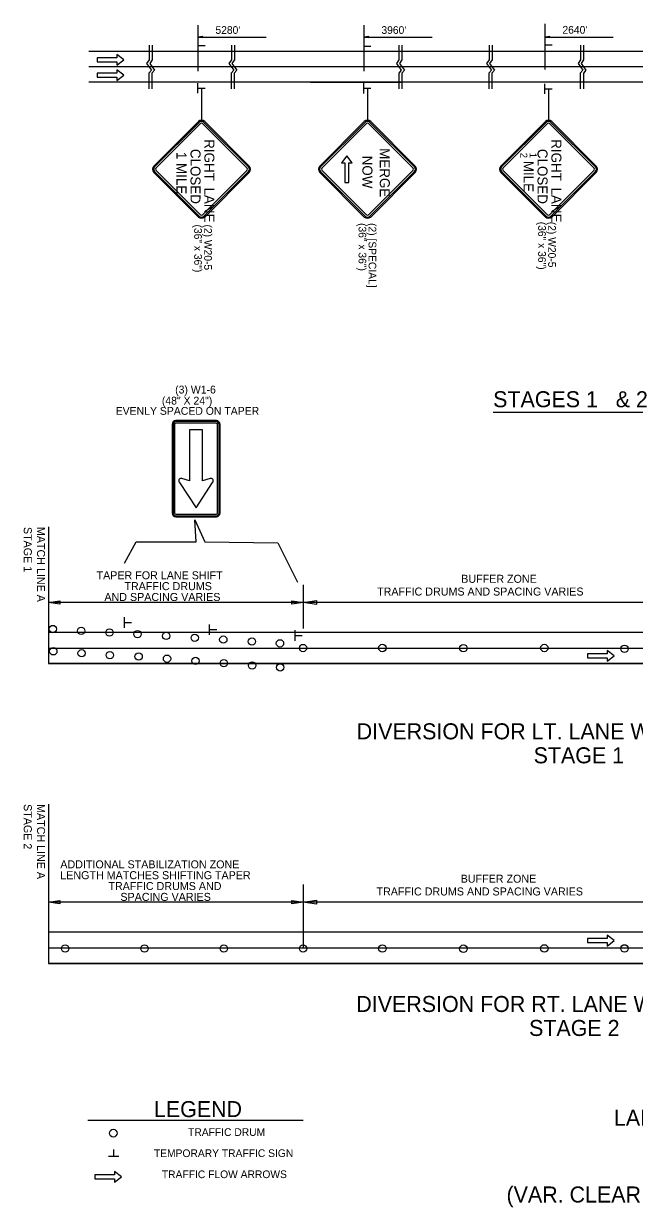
# Model space of a CAD drawing. Extents: x 1930579 to 1938745, y 596452 to 597559.
# Drawn here: x 1936678 to 1937136, y 596540 to 597428 of the extents above; entities that cross this region are included whole.
import ezdxf

# ---------------------------------------------------------------- set-up
doc = ezdxf.new("R2010")
doc.units = 0
for name, color, linetype in [('Default', 7, 'Continuous'), ('P_TC_Signs_Permanent', 7, 'Continuous'), ('P_TC_Signs_Temporary', 7, 'Continuous'), ('R_Annotation', 7, 'Continuous'), ('R_MOT', 7, 'Continuous'), ('R_Striping', 7, 'Continuous')]:
    doc.layers.add(name, color=color, linetype=linetype)

msp = doc.modelspace()

# ---------------------------------------------------------------- linework, layer by layer
at = {"layer": 'Default'}
for p, q in [((1936808.49, 597426.38), (1936808.49, 597391.9)), ((1936932.85, 597426.38), (1936932.85, 597391.9)), ((1937068.5, 597427.55), (1937068.5, 597393.08)), ((1936812.16, 597417.99), (1936808.49, 597417.44)), ((1936808.49, 597417.44), (1936859.59, 597417.44)), ((1936812.16, 597416.89), (1936808.49, 597417.44)), ((1936808.49, 597414.91), (1936808.49, 597407.25)), ((1936812.16, 597417.9), (1936809.1, 597417.44)), ((1936812.16, 597416.98), (1936809.1, 597417.44)), ((1936812.16, 597417.81), (1936809.73, 597417.44)), ((1936812.16, 597417.08), (1936809.73, 597417.44)), ((1936812.16, 597417.72), (1936810.34, 597417.44)), ((1936812.16, 597417.17), (1936810.34, 597417.44)), ((1936812.16, 597417.62), (1936810.96, 597417.44)), ((1936812.16, 597417.27), (1936810.96, 597417.44)), ((1936812.16, 597417.53), (1936811.58, 597417.44)), ((1936812.16, 597417.36), (1936811.58, 597417.44)), ((1936812.16, 597416.89), (1936812.16, 597417.99)), ((1936936.53, 597417.99), (1936932.85, 597417.44)), ((1936932.85, 597417.44), (1936983.96, 597417.44)), ((1936936.53, 597416.89), (1936932.85, 597417.44)), ((1936932.85, 597414.4), (1936932.85, 597406.74)), ((1936936.53, 597417.9), (1936933.47, 597417.44)), ((1936936.53, 597416.98), (1936933.47, 597417.44)), ((1936936.53, 597417.81), (1936934.1, 597417.44)), ((1936936.53, 597417.08), (1936934.1, 597417.44)), ((1936936.53, 597417.72), (1936934.71, 597417.44)), ((1936936.53, 597417.17), (1936934.71, 597417.44)), ((1936936.53, 597417.62), (1936935.33, 597417.44)), ((1936936.53, 597417.27), (1936935.33, 597417.44)), ((1936936.53, 597417.53), (1936935.95, 597417.44)), ((1936936.53, 597417.36), (1936935.95, 597417.44)), ((1936936.53, 597416.89), (1936936.53, 597417.99)), ((1937072.18, 597417.99), (1937068.5, 597417.44)), ((1937068.5, 597417.44), (1937119.61, 597417.44)), ((1937072.18, 597416.89), (1937068.5, 597417.44)), ((1937068.5, 597415.4), (1937068.5, 597407.74)), ((1937068.62, 597411.59), (1937073.85, 597411.59)), ((1937072.18, 597417.9), (1937069.12, 597417.44)), ((1937072.18, 597416.98), (1937069.12, 597417.44)), ((1937072.18, 597417.81), (1937069.75, 597417.44)), ((1937072.18, 597417.08), (1937069.75, 597417.44)), ((1937072.18, 597417.72), (1937070.36, 597417.44)), ((1937072.18, 597417.17), (1937070.36, 597417.44)), ((1937072.18, 597417.62), (1937070.98, 597417.44)), ((1937072.18, 597417.27), (1937070.98, 597417.44)), ((1937072.18, 597417.53), (1937071.6, 597417.44)), ((1937072.18, 597417.36), (1937071.6, 597417.44)), ((1937072.18, 597416.89), (1937072.18, 597417.99)), ((1937394.52, 597406.66), (1936726.79, 597406.66)), ((1936808.6, 597411.1), (1936813.83, 597411.1)), ((1936932.97, 597410.59), (1936938.2, 597410.59)), ((1938013.48, 597395.14), (1936726.79, 597395.14)), ((1937394.52, 597383.62), (1936726.79, 597383.62)), ((1936808.49, 597375.36), (1936808.49, 597383.02)), ((1936808.6, 597379.17), (1936813.83, 597379.17)), ((1936892.9, 597383.62), (1936960.47, 597383.62)), ((1936932.85, 597375.31), (1936932.85, 597382.97)), ((1936932.97, 597379.12), (1936938.2, 597379.12)), ((1937068.5, 597374.88), (1937068.5, 597382.54)), ((1937068.62, 597378.69), (1937073.85, 597378.69)), ((1937029.73, 597136.48), (1937158.05, 597136.48)), ((1936696.54, 597050.33), (1936696.54, 596947.87)), ((1936887.3, 597006.91), (1936887.3, 596974.28)), ((1936696.54, 596993.7), (1936705.03, 596994.97)), ((1936705.03, 596994.97), (1936705.03, 596992.42)), ((1936878.81, 596992.42), (1936878.81, 596994.97)), ((1936878.81, 596994.97), (1936887.3, 596993.7)), ((1936887.38, 596993.7), (1936897.44, 596995.21)), ((1936897.44, 596995.21), (1936897.44, 596992.19)), ((1936887.3, 596993.7), (1936696.54, 596993.7)), ((1936705.03, 596992.42), (1936696.54, 596993.7)), ((1936887.3, 596993.7), (1936878.81, 596992.42)), ((1937188.67, 596993.7), (1936887.3, 596993.7)), ((1936897.44, 596992.19), (1936887.38, 596993.7)), ((1936753.38, 596974.79), (1936753.38, 596982.58)), ((1936753.49, 596978.66), (1936758.81, 596978.66)), ((1936817.26, 596969.5), (1936817.26, 596977.29)), ((1937643.39, 596971.31), (1936696.54, 596971.31)), ((1936817.37, 596973.37), (1936822.69, 596973.37)), ((1936881.28, 596965.09), (1936881.28, 596972.88)), ((1936881.4, 596968.97), (1936886.72, 596968.97)), ((1936696.54, 596959.59), (1937643.39, 596959.59)), ((1936696.54, 596947.87), (1936970.48, 596947.87)), ((1937643.39, 596947.87), (1936696.54, 596947.87)), ((1936954.98, 596947.87), (1937223.6, 596947.87)), ((1936696.54, 596842.59), (1936696.54, 596723.17)), ((1936887.3, 596782.21), (1936887.3, 596734.89)), ((1936696.54, 596769), (1936705.03, 596770.27)), ((1936887.3, 596769), (1936696.54, 596769)), ((1936705.03, 596767.72), (1936696.54, 596769)), ((1936705.03, 596770.27), (1936705.03, 596767.72)), ((1936878.81, 596767.72), (1936878.81, 596770.27)), ((1936878.81, 596770.27), (1936887.3, 596769)), ((1936887.3, 596769), (1936878.81, 596767.72)), ((1937188.67, 596769), (1936887.3, 596769)), ((1936887.38, 596769), (1936897.44, 596770.51)), ((1936897.44, 596767.49), (1936887.38, 596769)), ((1936897.44, 596770.51), (1936897.44, 596767.49)), ((1937643.39, 596746.61), (1936696.54, 596746.61)), ((1936696.54, 596734.89), (1937643.39, 596734.89)), ((1936696.54, 596723.17), (1936970.48, 596723.17)), ((1937643.39, 596723.17), (1936696.54, 596723.17)), ((1936954.98, 596723.17), (1937223.6, 596723.17))]:
    msp.add_line(p, q, dxfattribs=at)
for points in [[(1936771.93, 597411.46), (1936771.93, 597400.51), (1936770.06, 597397.73), (1936773.71, 597392.74), (1936771.79, 597390.44), (1936771.79, 597378.82)], [(1936774.24, 597411.46), (1936774.24, 597400.41), (1936772.36, 597397.63), (1936776.01, 597392.65), (1936774.09, 597390.34), (1936774.09, 597378.82)], [(1936833.61, 597411.46), (1936833.61, 597400.51), (1936831.73, 597397.73), (1936835.38, 597392.74), (1936833.46, 597390.44), (1936833.46, 597378.82)], [(1936835.91, 597411.46), (1936835.91, 597400.41), (1936834.04, 597397.63), (1936837.68, 597392.65), (1936835.76, 597390.34), (1936835.76, 597378.82)], [(1936959.1, 597411.46), (1936959.1, 597400.51), (1936957.23, 597397.73), (1936960.88, 597392.74), (1936958.96, 597390.44), (1936958.95, 597378.82)], [(1936961.4, 597411.46), (1936961.4, 597400.41), (1936959.53, 597397.63), (1936963.18, 597392.65), (1936961.26, 597390.34), (1936961.26, 597378.82)], [(1937026.67, 597411.46), (1937026.67, 597400.51), (1937024.8, 597397.73), (1937028.44, 597392.74), (1937026.52, 597390.44), (1937026.52, 597378.82)], [(1937028.97, 597411.46), (1937028.97, 597400.41), (1937027.1, 597397.63), (1937030.74, 597392.65), (1937028.83, 597390.34), (1937028.82, 597378.82)], [(1937095.18, 597411.46), (1937095.18, 597400.51), (1937093.31, 597397.73), (1937096.95, 597392.74), (1937095.03, 597390.44), (1937095.03, 597378.82)], [(1937097.48, 597411.46), (1937097.48, 597400.41), (1937095.61, 597397.63), (1937099.25, 597392.65), (1937097.33, 597390.34), (1937097.33, 597378.82)]]:
    msp.add_lwpolyline(points, dxfattribs=at)
for centre, radius in [((1936699.79, 596973.82), 2.75), ((1936721.02, 596972.51), 2.75), ((1936742.25, 596971.19), 2.75), ((1936763.24, 596970.03), 2.75), ((1936784.68, 596968.65), 2.75), ((1936806.12, 596967.26), 2.75), ((1936827.55, 596965.88), 2.75), ((1936700.15, 596957.12), 2.75), ((1936848.99, 596964.5), 2.75), ((1936869.99, 596963.06), 2.75), ((1936887.3, 596959.59), 2.75), ((1936946.73, 596959.59), 2.8), ((1937007.41, 596959.44), 2.8), ((1937068.09, 596959.59), 2.8), ((1937128.13, 596959.01), 2.8), ((1936721.36, 596955.65), 2.75), ((1936742.58, 596954.17), 2.75), ((1936764.09, 596953.25), 2.75), ((1936785.37, 596951.58), 2.75), ((1936806.65, 596949.9), 2.75), ((1936827.93, 596948.22), 2.75), ((1936849.21, 596946.54), 2.75), ((1936870.19, 596945.08), 2.75), ((1936946.73, 596734.35), 2.8), ((1937068.09, 596734.41), 2.8), ((1937128.13, 596734.42), 2.8), ((1936709.01, 596734.35), 2.75), ((1936768.44, 596734.35), 2.75), ((1936827.87, 596734.35), 2.75), ((1936887.3, 596734.35), 2.75), ((1937007.41, 596734.21), 2.8), ((1936745.07, 596595.94), 2.88)]:
    msp.add_circle(centre, radius, dxfattribs=at)
at = {"layer": 'P_TC_Signs_Permanent'}
for p, q in [((1936822.32, 597129.99), (1936791.95, 597129.99)), ((1936822.32, 597129.24), (1936791.95, 597129.24)), ((1936822.32, 597128.12), (1936791.95, 597128.12)), ((1936789.13, 597127.18), (1936789.13, 597060.81)), ((1936789.88, 597127.18), (1936789.88, 597060.81)), ((1936791.01, 597127.18), (1936791.01, 597060.81)), ((1936823.26, 597060.81), (1936823.26, 597127.18)), ((1936824.38, 597060.81), (1936824.38, 597127.18)), ((1936825.13, 597060.81), (1936825.13, 597127.18)), ((1936791.95, 597059.87), (1936822.32, 597059.87)), ((1936791.95, 597058.74), (1936822.32, 597058.74)), ((1936791.95, 597057.99), (1936822.32, 597057.99))]:
    msp.add_line(p, q, dxfattribs=at)
for points in [[(1936817.77, 597086.7), (1936812.01, 597084.98), (1936812.01, 597123.24), (1936802.26, 597123.24), (1936802.26, 597084.98), (1936796.51, 597086.73)], [(1936794.69, 597083.74), (1936807.13, 597064.74), (1936819.54, 597083.75)]]:
    msp.add_lwpolyline(points, dxfattribs=at)
for centre, radius, start, end in [((1936791.95, 597127.18), 2.81, 90, 180), ((1936791.95, 597127.18), 2.06, 90, 180), ((1936791.95, 597127.18), 0.938, 90, 180), ((1936822.32, 597127.18), 2.81, 360, 90), ((1936822.32, 597127.18), 2.06, 360, 90), ((1936822.32, 597127.18), 0.937, 360, 90), ((1936796.02, 597085), 1.8, 74.03093, 213.47548), ((1936731.96, 597042.64), 75, 33.2286, 33.47548), ((1936818.25, 597085), 1.76, 326.59943, 105.96908), ((1936882.34, 597042.74), 75, 146.59943, 146.85697), ((1936791.95, 597060.81), 2.81, 180, 270), ((1936791.95, 597060.81), 2.06, 180, 270), ((1936791.95, 597060.81), 0.938, 180, 270), ((1936822.32, 597060.81), 2.81, 270, 360), ((1936822.32, 597060.81), 2.06, 270, 360), ((1936822.32, 597060.81), 0.938, 270, 360)]:
    msp.add_arc(centre, radius, start, end, dxfattribs=at)
at = {"layer": 'P_TC_Signs_Temporary'}
for p, q in [((1936775.42, 597320.83), (1936808.83, 597354.24)), ((1936776.08, 597320.16), (1936809.49, 597353.57)), ((1936777.01, 597319.23), (1936810.42, 597352.65)), ((1936812.01, 597352.65), (1936845.42, 597319.23)), ((1936812.94, 597353.57), (1936846.35, 597320.16)), ((1936813.6, 597354.24), (1936847.01, 597320.83)), ((1936899.78, 597320.83), (1936933.2, 597354.24)), ((1936900.45, 597320.16), (1936933.86, 597353.57)), ((1936901.38, 597319.23), (1936934.79, 597352.65)), ((1936936.38, 597352.65), (1936969.79, 597319.23)), ((1936937.31, 597353.57), (1936970.72, 597320.16)), ((1936937.97, 597354.24), (1936971.38, 597320.83)), ((1937035.43, 597320.83), (1937068.84, 597354.24)), ((1937036.1, 597320.16), (1937069.51, 597353.57)), ((1937037.03, 597319.23), (1937070.44, 597352.65)), ((1937072.03, 597352.65), (1937105.44, 597319.23)), ((1937072.95, 597353.57), (1937106.37, 597320.16)), ((1937073.62, 597354.24), (1937107.03, 597320.83)), ((1936808.83, 597282.64), (1936775.42, 597316.05)), ((1936809.49, 597283.3), (1936776.08, 597316.72)), ((1936810.42, 597284.23), (1936777.01, 597317.64)), ((1936845.42, 597317.64), (1936812.01, 597284.23)), ((1936846.35, 597316.72), (1936812.94, 597283.3)), ((1936847.01, 597316.05), (1936813.6, 597282.64)), ((1936933.2, 597282.64), (1936899.78, 597316.05)), ((1936933.86, 597283.3), (1936900.45, 597316.72)), ((1936934.79, 597284.23), (1936901.38, 597317.64)), ((1936969.79, 597317.64), (1936936.38, 597284.23)), ((1936970.72, 597316.72), (1936937.31, 597283.3)), ((1936971.38, 597316.05), (1936937.97, 597282.64)), ((1937068.84, 597282.64), (1937035.43, 597316.05)), ((1937069.51, 597283.3), (1937036.1, 597316.72)), ((1937070.44, 597284.23), (1937037.03, 597317.64)), ((1937105.44, 597317.64), (1937072.03, 597284.23)), ((1937106.37, 597316.72), (1937072.95, 597283.3)), ((1937107.03, 597316.05), (1937073.62, 597282.64))]:
    msp.add_line(p, q, dxfattribs=at)
for centre, radius, start, end in [((1936811.21, 597351.85), 3.37, 45, 135), ((1936811.21, 597351.85), 2.44, 45, 135), ((1936811.21, 597351.85), 1.12, 45, 135), ((1936935.58, 597351.85), 3.37, 45, 135), ((1936935.58, 597351.85), 2.44, 45, 135), ((1936935.58, 597351.85), 1.12, 45, 135), ((1937071.23, 597351.85), 3.37, 45, 135), ((1937071.23, 597351.85), 2.44, 45, 135), ((1937071.23, 597351.85), 1.12, 45, 135), ((1936777.8, 597318.44), 3.37, 135, 225), ((1936777.8, 597318.44), 2.44, 135, 225), ((1936777.8, 597318.44), 1.13, 135, 225), ((1936844.62, 597318.44), 1.13, 315, 45), ((1936844.62, 597318.44), 2.44, 315, 45), ((1936844.62, 597318.44), 3.38, 315, 45), ((1936902.17, 597318.44), 3.37, 135, 225), ((1936902.17, 597318.44), 2.44, 135, 225), ((1936902.17, 597318.44), 1.13, 135, 225), ((1936968.99, 597318.44), 1.13, 315, 45), ((1936968.99, 597318.44), 2.44, 315, 45), ((1936968.99, 597318.44), 3.38, 315, 45), ((1937037.82, 597318.44), 3.37, 135, 225), ((1937037.82, 597318.44), 2.44, 135, 225), ((1937037.82, 597318.44), 1.13, 135, 225), ((1937104.64, 597318.44), 1.13, 315, 45), ((1937104.64, 597318.44), 2.44, 315, 45), ((1937104.64, 597318.44), 3.37, 315, 45), ((1936811.21, 597285.03), 3.38, 225, 315), ((1936811.21, 597285.03), 2.44, 225, 315), ((1936811.21, 597285.03), 1.12, 225, 315), ((1936935.58, 597285.03), 3.38, 225, 315), ((1936935.58, 597285.03), 2.44, 225, 315), ((1936935.58, 597285.03), 1.12, 225, 315), ((1937071.23, 597285.03), 3.37, 225, 315), ((1937071.23, 597285.03), 2.44, 225, 315), ((1937071.23, 597285.03), 1.12, 225, 315)]:
    msp.add_arc(centre, radius, start, end, dxfattribs=at)
at = {"layer": 'R_Annotation'}
for p, q in [((1936811.21, 597379.17), (1936811.21, 597355.22)), ((1936935.58, 597379.12), (1936935.58, 597355.22)), ((1937071.23, 597378.69), (1937071.23, 597355.22)), ((1936726.09, 596605.58), (1936887.49, 596605.69)), ((1936749.26, 596578.39), (1936741.58, 596578.39)), ((1936745.44, 596578.5), (1936745.44, 596583.74))]:
    msp.add_line(p, q, dxfattribs=at)
msp.add_lwpolyline([(1936753.38, 597023.29), (1936762.17, 597039.21), (1936807.32, 597039.21), (1936806.15, 597055.7), (1936813.77, 597039.21), (1936868.47, 597038.42), (1936883.18, 597008.99)], dxfattribs=at)
at = {"layer": 'R_MOT'}
for points in [[(1936924.09, 597323.31), (1936920.09, 597328.5), (1936916.09, 597323.31), (1936918.59, 597323.31), (1936918.59, 597308.59), (1936921.59, 597308.59), (1936921.59, 597323.31)], [(1936746.07, 596559.17), (1936751.26, 596563.18), (1936746.07, 596567.17), (1936746.07, 596564.67), (1936731.36, 596564.66), (1936731.36, 596561.66), (1936746.07, 596561.67)]]:
    msp.add_lwpolyline(points, close=True, dxfattribs=at)
at = {"layer": 'R_Striping'}
for points in [[(1936747.79, 597396.34), (1936752.99, 597400.34), (1936747.79, 597404.34), (1936747.79, 597401.84), (1936733.08, 597401.84), (1936733.08, 597398.84), (1936747.79, 597398.84)], [(1936747.79, 597385.03), (1936752.99, 597389.03), (1936747.79, 597393.03), (1936747.79, 597390.53), (1936733.08, 597390.53), (1936733.08, 597387.53), (1936747.79, 597387.53)], [(1937115.13, 596949.68), (1937120.32, 596953.68), (1937115.13, 596957.68), (1937115.13, 596955.18), (1937100.41, 596955.18), (1937100.41, 596952.18), (1937115.13, 596952.18)], [(1937115.13, 596736.23), (1937120.32, 596740.23), (1937115.13, 596744.23), (1937115.13, 596741.73), (1937100.41, 596741.73), (1937100.41, 596738.73), (1937115.13, 596738.73)]]:
    msp.add_lwpolyline(points, close=True, dxfattribs=at)

# ---------------------------------------------------------------- texts
at = {"layer": 'Default'}
for s, height, rotation, p in [("5280'", 5.76, 360, (1936821.65, 597419.92)), ("3960'", 5.76, 360, (1936946.02, 597419.9)), ("2640'", 5.76, 360, (1937081.67, 597420.05)), ('STAGES 1   & 2', 12, 360, (1937029.73, 597140.05)), ('STAGE 1', 6, 270, (1936678.04, 597050.33)), ('MATCH LINE A ', 6, 270, (1936687.95, 597050.33)), ('TAPER FOR LANE SHIFT', 6, 360, (1936732.57, 597011.09)), ('BUFFER ZONE', 6, 360, (1937005.82, 597008.47)), ('TRAFFIC DRUMS ', 6, 360, (1936753.44, 597002.97)), ('TRAFFIC DRUMS AND SPACING VARIES', 6, 360, (1936942.76, 596998.9)), ('AND SPACING VARIES', 6, 360, (1936738.44, 596994.84)), ('DIVERSION FOR LT. LANE WORK ZONE', 12, 360, (1936927.5, 596891.14)), ('STAGE 1', 12, 360, (1937060.06, 596873.16)), ('STAGE 2', 6, 270, (1936678.04, 596842.59)), ('MATCH LINE A ', 6, 270, (1936687.95, 596842.59)), ('ADDITIONAL STABILIZATION ZONE', 6, 360, (1936705.41, 596794.42)), ('LENGTH MATCHES SHIFTING TAPER', 6, 360, (1936705.38, 596786.3)), ('TRAFFIC DRUMS AND ', 6, 360, (1936741.46, 596778.17)), ('BUFFER ZONE', 6, 360, (1937005.42, 596783.68)), ('SPACING VARIES', 6, 360, (1936750.44, 596770.04)), ('TRAFFIC DRUMS AND SPACING VARIES', 6, 360, (1936942.35, 596774.11)), ('DIVERSION FOR RT. LANE WORK ZONE', 12, 360, (1936927.21, 596686.77)), ('STAGE 2', 12, 360, (1937056.66, 596668.8)), ('LANE CLOSURE WITH TRAFFIC DRUMS', 12, 360, (1937120.24, 596601.57)), ('(VAR. CLEAR ROADWAY WIDTHS ON THE BRIDGE DECKS)', 12, 360, (1937039.74, 596543.97))]:
    msp.add_text(s, height=height, rotation=rotation, dxfattribs=at).set_placement(p)
at = {"layer": 'P_TC_Signs_Temporary'}
for s, height, p in [('CLOSED', 7.5, (1936802.96, 597333.69)), ('RIGHT\u2002LANE', 7.5, (1936813.34, 597340.96)), ('MERGE', 7.5, (1936944.79, 597334.2)), ('CLOSED', 7.5, (1937062.98, 597333.69)), ('RIGHT\u2002LANE', 7.5, (1937073.36, 597340.96)), ('1 MILE', 7.5, (1936792.46, 597331.49)), ('NOW', 7.5, (1936931.77, 597328.6)), ('2', 5.25, (1937050.11, 597330.79)), (' MILE', 7.5, (1937052.48, 597327.53)), ('1', 5.25, (1937057.11, 597330.79))]:
    msp.add_text(s, height=height, rotation=270, dxfattribs=at).set_placement(p)
at = {"layer": 'R_Annotation'}
for s, height, rotation, p in [('(36" x 36")', 5.76, 270, (1937063.47, 597279.07)), ('(2) W20-5', 5.76, 270, (1937070.96, 597279.07)), ('(36" x 36")', 5.76, 270, (1936805.73, 597277.02)), ('(2) W20-5', 5.76, 270, (1936813.22, 597277.02)), ('(36" x 36")', 5.76, 270, (1936928.89, 597278.09)), ('(2) [SPECIAL]', 5.76, 270, (1936936.38, 597278.09)), ('(3) W1-6', 5.859, 0.00754, (1936791.46, 597150.34)), ('(48" X 24")', 5.8594, 0.00754, (1936781.48, 597142.07)), ('EVENLY SPACED ON TAPER', 5.8594, 0.00754, (1936746.9, 597134.38)), ('LEGEND', 12, 0.03878, (1936775.57, 596607.95)), ('TRAFFIC DRUM', 5.76, 0.03876, (1936801.15, 596593.84)), ('TEMPORARY TRAFFIC SIGN', 5.76, 0.03876, (1936775.54, 596578.01)), ('TRAFFIC FLOW ARROWS', 5.76, 0.03876, (1936781.5, 596562.21))]:
    msp.add_text(s, height=height, rotation=rotation, dxfattribs=at).set_placement(p)

doc.saveas('drawing.dxf')
